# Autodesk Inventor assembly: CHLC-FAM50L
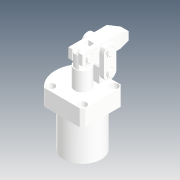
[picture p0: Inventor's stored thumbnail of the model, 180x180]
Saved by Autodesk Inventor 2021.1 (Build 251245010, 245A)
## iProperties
Created: 2019-04
Part Number: CHLC-FAM50L
Description: STEP AP214
Document SubType Name: Assembly
Designer: user
Title: CHLC-FAM50L.STEP
Revision Number: ÈÎºÎ
Sending System: SolidWorks 2016
Preprocessor: SwSTEP 2.0
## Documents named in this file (10)
- D:\Vault_2016\Projekty\Clamptek\Hydraulic\CHLC\CHLC-50\Inventor\CHLC-FAM50L\CHLC-FAM50L.iam
- D:\Vault_2016\Projekty\Clamptek\Hydraulic\CHLC\CHLC-50\Inventor\CHLC-FAM50L\CHLC-FAM50-±¾Ìå.ipt
- D:\Vault_2016\Projekty\Clamptek\Hydraulic\CHLC\CHLC-50\Inventor\CHLC-FAM50L\CHLC-50-01.ipt
- D:\Vault_2016\Projekty\Clamptek\Hydraulic\CHLC\CHLC-50\Inventor\CHLC-FAM50L\CHLC-50-02.ipt
- D:\Vault_2016\Projekty\Clamptek\Hydraulic\CHLC\CHLC-50\Inventor\CHLC-FAM50L\CHLC-50-03.ipt
- D:\Vault_2016\Projekty\Clamptek\Hydraulic\CHLC\CHLC-50\Inventor\CHLC-FAM50L\CHLC-50-04.ipt
- D:\Vault_2016\Projekty\Clamptek\Hydraulic\CHLC\CHLC-50\Inventor\CHLC-FAM50L\CHLC-50-06.ipt
- D:\Vault_2016\Projekty\Clamptek\Hydraulic\CHLC\CHLC-50\Inventor\CHLC-FAM50L\CHLC-50-09.ipt
- D:\Vault_2016\Projekty\Clamptek\Hydraulic\CHLC\CHLC-50\Inventor\CHLC-FAM50L\M6LS.ipt
- D:\Vault_2016\Projekty\Clamptek\Hydraulic\CHLC\CHLC-50\Inventor\CHLC-FAM50L\YAKUAI.ipt
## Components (17 placed, 17 different names)
1. CHLC-FAM50-±¾Ìå_1
2. CHLC-50-01_2
3. CHLC-50-02_3
4. CHLC-50-03_4
5. CHLC-50-04_5
6. CHLC-50-06_6
7. CHLC-50-09_7
8. M6LS_8
9. YAKUAI_9
10. CHLC-50-03_10
11. CHLC-50-06_11
12. CHLC-50-06_12
13. CHLC-50-06_13
14. CHLC-50-06_14
15. CHLC-50-06_15
16. CHLC-50-04_16
17. M6LS_17
